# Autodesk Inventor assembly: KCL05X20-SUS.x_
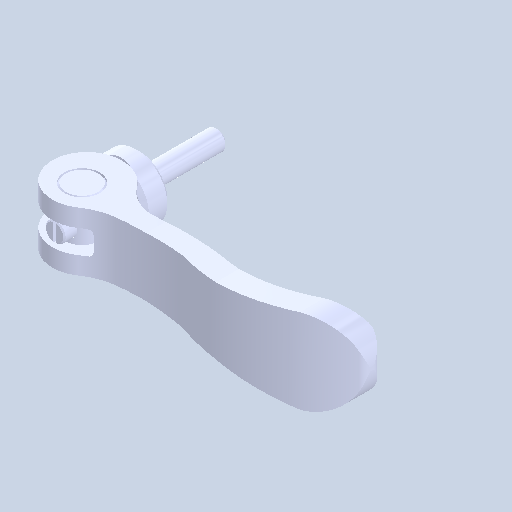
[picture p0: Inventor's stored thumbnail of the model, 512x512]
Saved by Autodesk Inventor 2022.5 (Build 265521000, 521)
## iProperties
Created: 2024-08
Part Number: KCL05X20-SUS.x_
Document SubType Name: Assembly
Designer: ImaoCorp
Author: ImaoCorp
Sending System: SOLIDWORKS 2022-2022290
MC: AMD64
MC_MODEL: Intel64 Family 6 Model 60 Stepping 3, GenuineIntel
OS: Windows_NT
FRU: Parasolid Version 33.1, build 260,  4-25-2022
FORMAT: text
GUISE: transmit
KEY: FILEKCL05X20-SUS.x_t
DATE: Thu Aug 29 10:49:01 2024
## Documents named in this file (5)
- Y:\5.更新分\2024年対応\1001_KCL\データ\kcl05x20-sus\KCL05X20-SUS.x_.iam
- Y:\5.更新分\2024年対応\1001_KCL\データ\kcl05x20-sus\KCL05X20-SUS_01.ipt
- Y:\5.更新分\2024年対応\1001_KCL\データ\kcl05x20-sus\KCL05X20-SUS_02.ipt
- Y:\5.更新分\2024年対応\1001_KCL\データ\kcl05x20-sus\KCL05X20-SUS_03.ipt
- Y:\5.更新分\2024年対応\1001_KCL\データ\kcl05x20-sus\KCL05X20-SUS_04.ipt
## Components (4 placed, 4 different names)
1. KCL05X20-SUS_01
2. KCL05X20-SUS_02
3. KCL05X20-SUS_03
4. KCL05X20-SUS_04
